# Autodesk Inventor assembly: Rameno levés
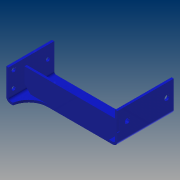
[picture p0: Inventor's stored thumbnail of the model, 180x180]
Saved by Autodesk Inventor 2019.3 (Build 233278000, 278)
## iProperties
Created: 2019-02
Part Number: Rameno levés
Material: Všeobecné
Document SubType Name: Assembly
Designer: B-hon
Author: B-hon
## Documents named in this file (3)
- C:\Users\B-hon\OneDrive\Plocha\Bakalářka22\Deska střední\Rameno levés.iam
- C:\Users\B-hon\OneDrive\Plocha\Bakalářka22\Deska střední\Rameno levés.ipt
- C:\Users\B-hon\OneDrive\Plocha\Bakalářka22\Deska střední\Výztuha ramene s.ipt
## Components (2 placed, 2 different names)
1. Rameno levés:1 — Proti sobě:1, Stejný směr:1, Proti sobě:2
2. Výztuha ramene s:1 — Proti sobě:1, Stejný směr:1, Proti sobě:2
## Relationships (3: Mate 2, Flush 1)
- Proti sobě:1 [Mate]: Rameno levés:1 ↔ Výztuha ramene s:1
- Stejný směr:1 [Flush]: Rameno levés:1 ↔ Výztuha ramene s:1
- Proti sobě:2 [Mate]: Rameno levés:1 ↔ Výztuha ramene s:1
